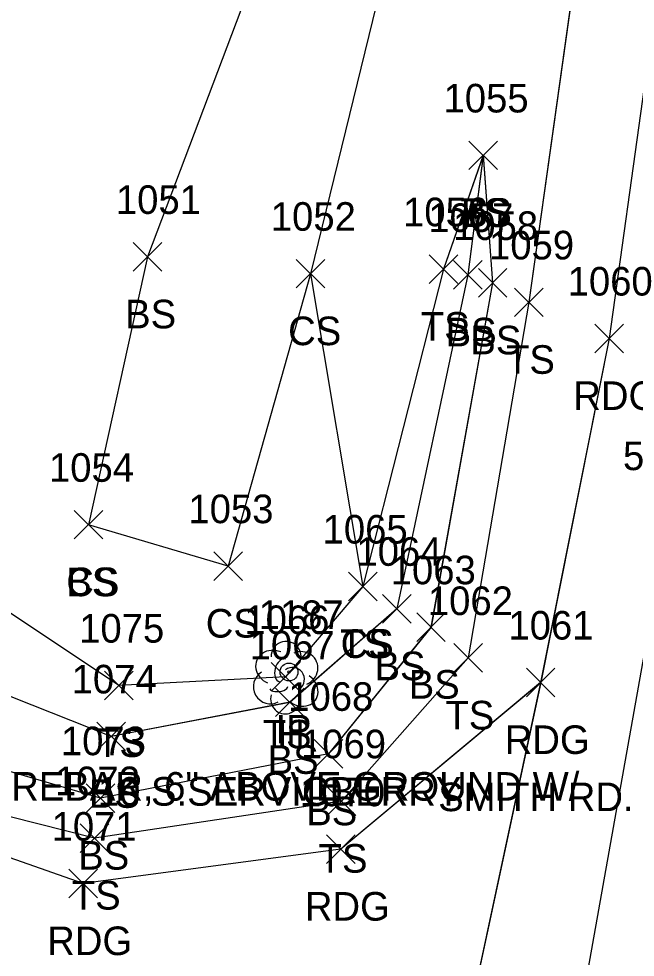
# Model space of a CAD drawing. Extents: x 1554668 to 1563881, y 831386 to 834374.
# Drawn here: x 1561889.7 to 1561932.8, y 834064.9 to 834130.6 of the extents above; entities that cross this region are included whole.
import ezdxf

# ---------------------------------------------------------------- set-up
doc = ezdxf.new("R2010")
doc.units = 0
for name, color, linetype in [('L_A', 7, 'Continuous'), ('L_C', 7, 'Continuous'), ('L_I', 7, 'Continuous'), ('L_TIC', 7, 'Continuous'), ('LELB', 7, 'Continuous'), ('LTD', 7, 'Continuous'), ('M_A', 7, 'Continuous'), ('M_C', 7, 'Continuous'), ('M_I', 7, 'Continuous'), ('MPIR', 7, 'Continuous'), ('P_A', 7, 'Continuous'), ('P_C', 7, 'Continuous'), ('P_I', 7, 'Continuous'), ('P_TIC', 7, 'Continuous'), ('PEU', 7, 'Continuous'), ('PRC', 7, 'Continuous')]:
    doc.layers.add(name, color=color, linetype=linetype)

msp = doc.modelspace()

# ---------------------------------------------------------------- linework, layer by layer
at = {"layer": 'L_TIC'}
for points in [[(1561921.177, 834120.01), (1561923.177, 834122.01)], [(1561923.177, 834120.01), (1561921.177, 834122.01)], [(1561921.177, 834120.01), (1561923.177, 834122.01)], [(1561923.177, 834120.01), (1561921.177, 834122.01)], [(1561921.177, 834120.01), (1561923.177, 834122.01)], [(1561923.177, 834120.01), (1561921.177, 834122.01)], [(1561897.697, 834112.913), (1561899.697, 834114.913)], [(1561899.697, 834112.913), (1561897.697, 834114.913)], [(1561897.697, 834112.913), (1561899.697, 834114.913)], [(1561899.697, 834112.913), (1561897.697, 834114.913)], [(1561909.096, 834111.736), (1561911.096, 834113.736)], [(1561911.096, 834111.736), (1561909.096, 834113.736)], [(1561909.096, 834111.736), (1561911.096, 834113.736)], [(1561911.096, 834111.736), (1561909.096, 834113.736)], [(1561918.403, 834112.051), (1561920.403, 834114.051)], [(1561920.403, 834112.051), (1561918.403, 834114.051)], [(1561920.113, 834111.652), (1561922.113, 834113.652)], [(1561922.113, 834111.652), (1561920.113, 834113.652)], [(1561921.839, 834111.092), (1561923.839, 834113.092)], [(1561923.839, 834111.092), (1561921.839, 834113.092)], [(1561924.366, 834109.733), (1561926.366, 834111.733)], [(1561926.366, 834109.733), (1561924.366, 834111.733)], [(1561893.582, 834094.182), (1561895.582, 834096.182)], [(1561895.582, 834094.182), (1561893.582, 834096.182)], [(1561893.582, 834094.182), (1561895.582, 834096.182)], [(1561895.582, 834094.182), (1561893.582, 834096.182)], [(1561903.336, 834091.287), (1561905.336, 834093.287)], [(1561905.336, 834091.287), (1561903.336, 834093.287)], [(1561912.766, 834089.863), (1561914.766, 834091.863)], [(1561914.766, 834089.863), (1561912.766, 834091.863)], [(1561912.766, 834089.863), (1561914.766, 834091.863)], [(1561914.766, 834089.863), (1561912.766, 834091.863)], [(1561915.134, 834088.306), (1561917.134, 834090.306)], [(1561917.134, 834088.306), (1561915.134, 834090.306)], [(1561917.528, 834087.015), (1561919.528, 834089.015)], [(1561919.528, 834087.015), (1561917.528, 834089.015)], [(1561920.128, 834084.862), (1561922.128, 834086.862)], [(1561922.128, 834084.862), (1561920.128, 834086.862)], [(1561907.349, 834083.533), (1561909.349, 834085.533)], [(1561909.349, 834083.533), (1561907.349, 834085.533)], [(1561895.696, 834082.934), (1561897.696, 834084.934)], [(1561897.696, 834082.934), (1561895.696, 834084.934)], [(1561907.665, 834081.758), (1561909.665, 834083.758)], [(1561909.665, 834081.758), (1561907.665, 834083.758)], [(1561895.17, 834079.381), (1561897.17, 834081.381)], [(1561897.17, 834079.381), (1561895.17, 834081.381)], [(1561910.364, 834078.162), (1561912.364, 834080.162)], [(1561912.364, 834078.162), (1561910.364, 834080.162)], [(1561894.418, 834075.06), (1561896.418, 834077.06)], [(1561896.418, 834075.06), (1561894.418, 834077.06)], [(1561911.262, 834074.847), (1561913.262, 834076.847)], [(1561913.262, 834074.847), (1561911.262, 834076.847)], [(1561894, 834072.266), (1561896, 834074.266)], [(1561896, 834072.266), (1561894, 834074.266)]]:
    msp.add_lwpolyline(points, dxfattribs=at)
at = {"layer": 'LELB'}
for points in [[(1561919.078, 834295.725), (1561941.402, 834267.956), (1561947.693, 834240.533), (1561943.692, 834200.785), (1561932.657, 834162.632), (1561925.366, 834110.733), (1561921.128, 834085.862), (1561912.262, 834075.847), (1561895, 834073.266), (1561871.203, 834079.274), (1561849.665, 834090.243), (1561839.973, 834096.347), (1561824.095, 834104.801)], [(1561919.077, 834295.724), (1561941.402, 834267.957), (1561947.69, 834240.53), (1561943.694, 834200.787), (1561932.654, 834162.63), (1561925.364, 834110.732), (1561921.13, 834085.862), (1561912.259, 834075.847), (1561894.999, 834073.266), (1561871.203, 834079.274), (1561849.664, 834090.243), (1561839.972, 834096.346), (1561824.095, 834104.806)], [(1561919.077, 834295.724), (1561941.402, 834267.957), (1561947.69, 834240.53), (1561943.694, 834200.787), (1561932.654, 834162.63), (1561925.364, 834110.732), (1561921.13, 834085.862), (1561912.259, 834075.847), (1561894.999, 834073.266), (1561871.203, 834079.274), (1561849.664, 834090.243), (1561839.972, 834096.346), (1561824.095, 834104.806)], [(1561919.077, 834295.724), (1561941.402, 834267.957), (1561947.69, 834240.53), (1561943.694, 834200.787), (1561932.654, 834162.63), (1561925.364, 834110.732), (1561921.13, 834085.862), (1561912.259, 834075.847), (1561894.999, 834073.266), (1561871.203, 834079.274), (1561849.664, 834090.243), (1561839.972, 834096.346), (1561824.095, 834104.806)], [(1561915.795, 834287.642), (1561934.969, 834260.007), (1561939.221, 834238.432), (1561923.537, 834223.21), (1561902.684, 834216.876), (1561894.283, 834202.79), (1561919.96, 834201.267), (1561917.708, 834164.146), (1561898.697, 834113.913)], [(1561915.794, 834287.64), (1561934.968, 834260.007), (1561939.221, 834238.433), (1561923.534, 834223.207), (1561902.682, 834216.872), (1561894.284, 834202.793), (1561919.962, 834201.27), (1561917.705, 834164.144), (1561898.696, 834113.913)], [(1561915.794, 834287.64), (1561934.968, 834260.007), (1561939.221, 834238.433), (1561923.534, 834223.207), (1561902.682, 834216.872), (1561894.284, 834202.793), (1561919.962, 834201.27), (1561917.705, 834164.144), (1561898.696, 834113.913)], [(1561915.794, 834287.64), (1561934.968, 834260.007), (1561939.221, 834238.433), (1561923.534, 834223.207), (1561902.682, 834216.872), (1561894.284, 834202.793), (1561919.962, 834201.27), (1561917.705, 834164.144), (1561898.696, 834113.913)], [(1561939.221, 834238.432), (1561939.841, 834223.118), (1561927.744, 834220.525), (1561906.689, 834208.129), (1561921.185, 834205.836), (1561939.722, 834201.577), (1561922.594, 834163.798), (1561910.096, 834112.736), (1561913.766, 834090.863)], [(1561939.221, 834238.433), (1561939.838, 834223.115), (1561927.744, 834220.525), (1561906.691, 834208.131), (1561921.185, 834205.835), (1561939.725, 834201.58), (1561922.591, 834163.795), (1561910.097, 834112.736), (1561913.767, 834090.864)], [(1561939.221, 834238.433), (1561939.838, 834223.115), (1561927.744, 834220.525), (1561906.691, 834208.131), (1561921.185, 834205.835), (1561939.725, 834201.58), (1561922.591, 834163.795), (1561910.097, 834112.736), (1561913.767, 834090.864)], [(1561939.221, 834238.433), (1561939.838, 834223.115), (1561927.744, 834220.525), (1561906.691, 834208.131), (1561921.185, 834205.835), (1561939.725, 834201.58), (1561922.591, 834163.795), (1561910.097, 834112.736), (1561913.767, 834090.864)], [(1561922.177, 834121.01), (1561922.839, 834112.092), (1561918.528, 834088.015), (1561911.364, 834079.162), (1561895.418, 834076.06), (1561873.102, 834082.615), (1561851.175, 834092.425), (1561850.092, 834109.008)], [(1561922.18, 834121.012), (1561922.836, 834112.091), (1561918.532, 834088.016), (1561911.367, 834079.163), (1561895.418, 834076.06), (1561873.104, 834082.616), (1561851.174, 834092.424), (1561850.093, 834109.01)], [(1561922.18, 834121.012), (1561922.836, 834112.091), (1561918.532, 834088.016), (1561911.367, 834079.163), (1561895.418, 834076.06), (1561873.104, 834082.616), (1561851.174, 834092.424), (1561850.093, 834109.01)], [(1561922.18, 834121.012), (1561922.836, 834112.091), (1561918.532, 834088.016), (1561911.367, 834079.163), (1561895.418, 834076.06), (1561873.104, 834082.616), (1561851.174, 834092.424), (1561850.093, 834109.01)], [(1561922.18, 834121.012), (1561921.112, 834112.652), (1561916.132, 834089.306), (1561908.668, 834082.759), (1561896.169, 834080.381), (1561878.1, 834087.522), (1561854.134, 834096.818), (1561853.235, 834109.481)], [(1561922.18, 834121.012), (1561921.112, 834112.652), (1561916.132, 834089.306), (1561908.668, 834082.759), (1561896.169, 834080.381), (1561878.1, 834087.522), (1561854.134, 834096.818), (1561853.235, 834109.481)], [(1561922.18, 834121.012), (1561921.112, 834112.652), (1561916.132, 834089.306), (1561908.668, 834082.759), (1561896.169, 834080.381), (1561878.1, 834087.522), (1561854.134, 834096.818), (1561853.235, 834109.481)], [(1561922.177, 834121.01), (1561921.113, 834112.652), (1561916.134, 834089.306), (1561908.665, 834082.758), (1561896.17, 834080.381), (1561878.102, 834087.523), (1561854.131, 834096.815), (1561853.235, 834109.481)], [(1561922.18, 834121.012), (1561919.4, 834113.05), (1561913.767, 834090.864), (1561908.345, 834084.533), (1561896.7, 834083.935), (1561882.108, 834093.657), (1561858.454, 834104.24), (1561855.003, 834109.434)], [(1561922.18, 834121.012), (1561919.4, 834113.05), (1561913.767, 834090.864), (1561908.345, 834084.533), (1561896.7, 834083.935), (1561882.108, 834093.657), (1561858.454, 834104.24), (1561855.003, 834109.434)], [(1561922.18, 834121.012), (1561919.4, 834113.05), (1561913.767, 834090.864), (1561908.345, 834084.533), (1561896.7, 834083.935), (1561882.108, 834093.657), (1561858.454, 834104.24), (1561855.003, 834109.434)], [(1561922.177, 834121.01), (1561919.403, 834113.051), (1561913.766, 834090.863), (1561908.349, 834084.533), (1561896.696, 834083.934), (1561882.106, 834093.656), (1561858.457, 834104.243), (1561855.004, 834109.434)], [(1561898.696, 834113.913), (1561894.579, 834095.181)], [(1561898.696, 834113.913), (1561894.579, 834095.181)], [(1561898.696, 834113.913), (1561894.579, 834095.181)], [(1561898.697, 834113.913), (1561894.582, 834095.182)], [(1561910.097, 834112.736), (1561904.337, 834092.287), (1561894.579, 834095.181)], [(1561910.097, 834112.736), (1561904.337, 834092.287), (1561894.579, 834095.181)], [(1561910.097, 834112.736), (1561904.337, 834092.287), (1561894.579, 834095.181)], [(1561910.096, 834112.736), (1561904.336, 834092.287), (1561894.582, 834095.182)]]:
    msp.add_lwpolyline(points, dxfattribs=at)
at = {"layer": 'LTD'}
msp.add_line((1561908.349, 834084.533), (1561908.349, 834084.533), dxfattribs=at)
msp.add_line((1561908.349, 834084.533), (1561908.349, 834084.533), dxfattribs=at)
msp.add_arc((1561908.396, 834085.967), 1.047, 335.52715, 180.95627, dxfattribs=at)
for centre, major_axis, ratio, start_param, end_param in [((1561907.558, 834085.2), (1.21, -0.512), 0.895232, 1.570796, 4.712389), ((1561909.391, 834085.117), (-1.141, -0.483), 0.949671, 1.570796, 4.712389), ((1561908.141, 834084.992), (-0.208, -0.792), 0.645439, 3.141593, 6.283185), ((1561907.266, 834083.825), (0.584, -1.042), 0.959034, 3.141593, 6.283185), ((1561908.849, 834084.367), (-0.5, 0.667), 0.989748, 3.141593, 6.283185), ((1561909.35, 834083.7), (-1.09, 0.792), 0.841452, 1.570796, 4.712389), ((1561907.891, 834083.783), (-0.625, -0.083), 0.423636, 0, 3.141593), ((1561908.35, 834083.033), (0.265, 1.061), 0.942809, 1.570796, 4.712389)]:
    msp.add_ellipse(centre, major_axis=major_axis, ratio=ratio, start_param=start_param, end_param=end_param, dxfattribs=at)
at = {"layer": 'MPIR'}
for radius in [0.625, 0.0833]:
    msp.add_circle((1561908.601, 834084.883), radius, dxfattribs=at)
at = {"layer": 'P_TIC'}
for points in [[(1561929.989, 834107.205), (1561931.989, 834109.205)], [(1561931.989, 834107.205), (1561929.989, 834109.205)], [(1561925.196, 834083.148), (1561927.196, 834085.148)], [(1561927.196, 834083.148), (1561925.196, 834085.148)], [(1561925.196, 834083.148), (1561927.196, 834085.148)], [(1561927.196, 834083.148), (1561925.196, 834085.148)], [(1561911.217, 834071.493), (1561913.217, 834073.493)], [(1561913.217, 834071.493), (1561911.217, 834073.493)], [(1561893.201, 834069.082), (1561895.201, 834071.082)], [(1561895.201, 834069.082), (1561893.201, 834071.082)]]:
    msp.add_lwpolyline(points, dxfattribs=at)
at = {"layer": 'PEU'}
for points in [[(1561919.943, 834298.234), (1561943.28, 834270.95), (1561951.487, 834242.498), (1561947.428, 834199.982), (1561938.335, 834160.955), (1561930.989, 834108.205), (1561926.196, 834084.148), (1561918.625, 834048.817), (1561911.303, 834007.014), (1561902.907, 833960.116), (1561894.327, 833910.706), (1561885.392, 833863.263), (1561878.367, 833822.842), (1561871.83, 833787.475), (1561866.706, 833759.336), (1561861.912, 833735.821)], [(1561919.942, 834298.234), (1561943.28, 834270.951), (1561951.486, 834242.497), (1561947.431, 834199.985), (1561938.334, 834160.954), (1561930.992, 834108.207), (1561926.199, 834084.149), (1561918.629, 834048.816), (1561911.301, 834007.016), (1561902.906, 833960.119), (1561894.326, 833910.708), (1561885.391, 833863.267), (1561878.367, 833822.843), (1561871.83, 833787.477), (1561866.708, 833759.341), (1561861.913, 833735.821)], [(1561919.942, 834298.234), (1561943.28, 834270.951), (1561951.486, 834242.497), (1561947.431, 834199.985), (1561938.334, 834160.954), (1561930.992, 834108.207), (1561926.199, 834084.149), (1561918.629, 834048.816), (1561911.301, 834007.016), (1561902.906, 833960.119), (1561894.326, 833910.708), (1561885.391, 833863.267), (1561878.367, 833822.843), (1561871.83, 833787.477), (1561866.708, 833759.341), (1561861.913, 833735.821)], [(1561919.942, 834298.234), (1561943.28, 834270.951), (1561951.486, 834242.497), (1561947.431, 834199.985), (1561938.334, 834160.954), (1561930.992, 834108.207), (1561926.199, 834084.149), (1561918.629, 834048.816), (1561911.301, 834007.016), (1561902.906, 833960.119), (1561894.326, 833910.708), (1561885.391, 833863.267), (1561878.367, 833822.843), (1561871.83, 833787.477), (1561866.708, 833759.341), (1561861.913, 833735.821)], [(1561926.199, 834084.149), (1561912.219, 834072.494), (1561894.201, 834070.082), (1561870.637, 834078.374), (1561848.112, 834088.834), (1561822.735, 834103.211)], [(1561926.199, 834084.149), (1561912.219, 834072.494), (1561894.201, 834070.082), (1561870.637, 834078.374), (1561848.112, 834088.834), (1561822.735, 834103.211)], [(1561926.199, 834084.149), (1561912.219, 834072.494), (1561894.201, 834070.082), (1561870.637, 834078.374), (1561848.112, 834088.834), (1561822.735, 834103.211)], [(1561926.196, 834084.148), (1561912.217, 834072.493), (1561894.201, 834070.082), (1561870.636, 834078.374), (1561848.111, 834088.833), (1561822.736, 834103.213)]]:
    msp.add_lwpolyline(points, dxfattribs=at)
at = {"layer": 'PRC'}
for points in [[(1561800.21, 833371.538), (1561806.437, 833405.192), (1561812.654, 833434.931), (1561820.127, 833472.189), (1561827.528, 833505.749), (1561836.938, 833558.608), (1561848.037, 833617.29), (1561858.182, 833669.762), (1561866.962, 833717.246), (1561878.604, 833773.781), (1561885.024, 833806.831), (1561891.658, 833847.81), (1561899.783, 833893.72), (1561902.023, 833902.922), (1561908.115, 833944.075), (1561914.56, 833974.526), (1561922.248, 834021.375), (1561927.368, 834052.029), (1561935.214, 834095.998), (1561945.529, 834150.774)], [(1561800.212, 833371.537), (1561806.439, 833405.19), (1561812.656, 833434.927), (1561820.128, 833472.18), (1561827.529, 833505.744), (1561836.939, 833558.603), (1561848.037, 833617.288), (1561858.18, 833669.759), (1561866.961, 833717.243), (1561878.605, 833773.781), (1561885.024, 833806.829), (1561891.662, 833847.808), (1561899.784, 833893.716), (1561902.024, 833902.921), (1561908.116, 833944.071), (1561914.561, 833974.522), (1561922.249, 834021.372), (1561927.371, 834052.029), (1561935.212, 834095.998), (1561945.527, 834150.773)], [(1561800.212, 833371.537), (1561806.439, 833405.19), (1561812.656, 833434.927), (1561820.128, 833472.18), (1561827.529, 833505.744), (1561836.939, 833558.603), (1561848.037, 833617.288), (1561858.18, 833669.759), (1561866.961, 833717.243), (1561878.605, 833773.781), (1561885.024, 833806.829), (1561891.662, 833847.808), (1561899.784, 833893.716), (1561902.024, 833902.921), (1561908.116, 833944.071), (1561914.561, 833974.522), (1561922.249, 834021.372), (1561927.371, 834052.029), (1561935.212, 834095.998), (1561945.527, 834150.773)], [(1561800.212, 833371.537), (1561806.439, 833405.19), (1561812.656, 833434.927), (1561820.128, 833472.18), (1561827.529, 833505.744), (1561836.939, 833558.603), (1561848.037, 833617.288), (1561858.18, 833669.759), (1561866.961, 833717.243), (1561878.605, 833773.781), (1561885.024, 833806.829), (1561891.662, 833847.808), (1561899.784, 833893.716), (1561902.024, 833902.921), (1561908.116, 833944.071), (1561914.561, 833974.522), (1561922.249, 834021.372), (1561927.371, 834052.029), (1561935.212, 834095.998), (1561945.527, 834150.773)]]:
    msp.add_lwpolyline(points, dxfattribs=at)

# ---------------------------------------------------------------- texts
at = {"layer": 'L_A'}
for s, p in [('TS', (1561920.586, 834116.01)), ('BS', (1561920.618, 834116.01)), ('BS', (1561920.618, 834116.01)), ('BS', (1561897.138, 834108.913)), ('BS', (1561897.138, 834108.913)), ('CS', (1561908.537, 834107.736)), ('CS', (1561908.537, 834107.736)), ('TS', (1561917.813, 834108.051)), ('BS', (1561919.553, 834107.652)), ('BS', (1561921.28, 834107.092)), ('TS', (1561923.775, 834105.733)), ('CS', (1561893.022, 834090.182)), ('BS', (1561893.022, 834090.182)), ('CS', (1561902.777, 834087.287)), ('TS', (1561912.175, 834085.863)), ('CS', (1561912.207, 834085.863)), ('BS', (1561914.575, 834084.306)), ('BS', (1561916.969, 834083.015)), ('TS', (1561919.537, 834080.862)), ('TS', (1561906.759, 834079.533)), ('H', (1561907.782, 834079.533)), ('TS', (1561895.105, 834078.934)), ('BS', (1561907.106, 834077.758)), ('BS', (1561894.611, 834075.381)), ('BS', (1561909.805, 834074.162)), ('BS', (1561893.859, 834071.06)), ('TS', (1561910.671, 834070.847)), ('TS', (1561893.41, 834068.266))]:
    msp.add_text(s, height=2, dxfattribs=at).set_placement(p)
at = {"layer": 'L_C'}
msp.add_text('10 S.SERVICBERRY', height=2, dxfattribs=at).set_placement((1561895.231, 834075.533))
at = {"layer": 'L_I'}
for s, p in [('1055', (1561919.405, 834124.01)), ('1055', (1561919.405, 834124.01)), ('1055', (1561919.405, 834124.01)), ('1051', (1561896.492, 834116.913)), ('1051', (1561896.492, 834116.913)), ('1052', (1561907.325, 834115.736)), ('1052', (1561907.325, 834115.736)), ('1056', (1561916.576, 834116.051)), ('1057', (1561918.341, 834115.652)), ('1058', (1561920.067, 834115.092)), ('1059', (1561922.586, 834113.733)), ('1054', (1561891.81, 834098.182)), ('1054', (1561891.81, 834098.182)), ('1053', (1561901.564, 834095.287)), ('1065', (1561910.947, 834093.863)), ('1065', (1561910.947, 834093.863)), ('1064', (1561913.315, 834092.306)), ('1063', (1561915.71, 834091.015)), ('1062', (1561918.309, 834088.862)), ('1066', (1561905.475, 834087.533)), ('1066', (1561905.475, 834087.533)), ('1075', (1561893.924, 834086.934)), ('1067', (1561905.846, 834085.758)), ('1074', (1561893.398, 834083.381)), ('1068', (1561908.545, 834082.162)), ('1073', (1561892.646, 834079.06)), ('1069', (1561909.435, 834078.847)), ('1072', (1561892.229, 834076.266))]:
    msp.add_text(s, height=2, dxfattribs=at).set_placement(p)
at = {"layer": 'M_A'}
msp.add_text('IP', height=2, dxfattribs=at).set_placement((1561907.648, 834079.883))
at = {"layer": 'M_C'}
msp.add_text('1/2" REBAR, 6" ABOVE GROUND W/', height=2, dxfattribs=at).set_placement((1561883.758, 834075.883))
at = {"layer": 'M_I'}
msp.add_text('1187', height=2, dxfattribs=at).set_placement((1561906.475, 834087.883))
at = {"layer": 'P_A'}
for p in [(1561928.477, 834103.205), (1561923.684, 834079.148), (1561923.684, 834079.148), (1561909.706, 834067.493), (1561891.689, 834065.082)]:
    msp.add_text('RDG', height=2, dxfattribs=at).set_placement(p)
at = {"layer": 'P_C'}
msp.add_text('SMITH RD.', height=2, dxfattribs=at).set_placement((1561919.03, 834075.148))
msp.add_text('SMITH RD.', height=2, dxfattribs=at).set_placement((1561919.03, 834075.148))
at = {"layer": 'P_I'}
for s, p in [('1060', (1561928.084, 834111.205)), ('5982', (1561931.954, 834098.998)), ('1061', (1561923.944, 834087.148)), ('1061', (1561923.944, 834087.148)), ('1070', (1561909.359, 834075.493)), ('1071', (1561891.997, 834073.082))]:
    msp.add_text(s, height=2, dxfattribs=at).set_placement(p)

doc.saveas('drawing.dxf')
